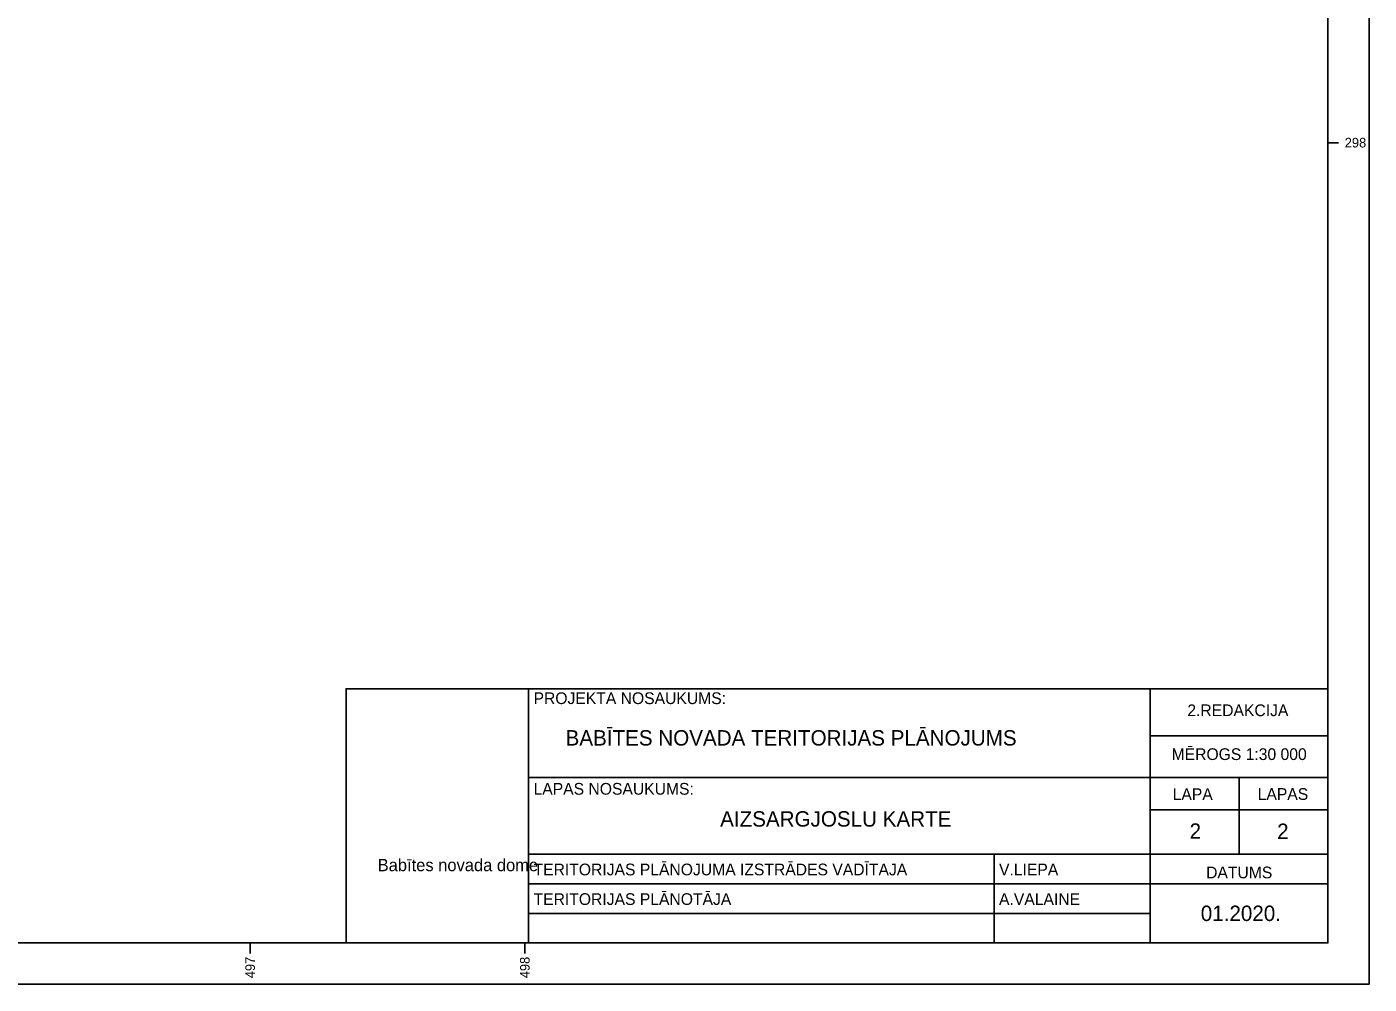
# Model space of a CAD drawing. Extents: x 468834 to 503362, y 294936 to 320859.
# Drawn here: x 496187 to 501073, y 294936 to 298422 of the extents above; entities that cross this region are included whole.
import ezdxf

# ---------------------------------------------------------------- set-up
doc = ezdxf.new("R2010")
doc.units = 0
doc.layers.add('ramis', color=7, linetype='Continuous')
doc.layers.add('Teksts', color=7, linetype='Continuous')

msp = doc.modelspace()

# ---------------------------------------------------------------- linework, layer by layer
at = {"layer": 'ramis'}
for p, q in [((500923.3, 316660.3), (500923.3, 295086.2)), ((500923.3, 298000), (500961.5, 298000)), ((500276.6, 296011.6), (498013.4, 296011.6)), ((500276.6, 296011.6), (500923.3, 296011.6)), ((500923.3, 296011.6), (500923.3, 295409.6)), ((498013.4, 295409.6), (498013.4, 295840.7)), ((498013.4, 295688.3), (500276.6, 295688.3)), ((500276.6, 295688.3), (500923.3, 295688.3)), ((500276.6, 295688.3), (500600, 295688.3)), ((500276.6, 295688.3), (500600, 295688.3)), ((500600, 295688.3), (500600, 295409.6)), ((500600, 295688.3), (500923.3, 295688.3)), ((500276.6, 295570.9), (500923.3, 295570.9)), ((499708.1, 295409.6), (498013.4, 295409.6)), ((498013.4, 295409.6), (498013.4, 295301.8)), ((499708.1, 295301.8), (499708.1, 295409.6)), ((500276.6, 295409.6), (499708.1, 295409.6)), ((500923.3, 295409.6), (500276.6, 295409.6)), ((500923.3, 295301.8), (500923.3, 295409.6)), ((499708.1, 295301.8), (498013.4, 295301.8)), ((498013.4, 295301.8), (498013.4, 295194)), ((498013.4, 295301.8), (499708.1, 295301.8)), ((499708.1, 295194), (499708.1, 295301.8)), ((500276.6, 295301.8), (499708.1, 295301.8)), ((499708.1, 295301.8), (500276.6, 295301.8)), ((500276.6, 295301.8), (500923.3, 295301.8)), ((500923.3, 295194), (500923.3, 295301.8)), ((500923.3, 295086.2), (500923.3, 295240.2)), ((500923.3, 295240.2), (500923.3, 295086.2)), ((500923.3, 295086.2), (500923.3, 295240.2)), ((498013.4, 295194), (498013.4, 295086.2)), ((498013.4, 295086.2), (498013.4, 295194)), ((499708.1, 295194), (498013.4, 295194)), ((498013.4, 295194), (498013.4, 295086.2)), ((498013.4, 295194), (499708.1, 295194)), ((499708.1, 295086.2), (499708.1, 295194)), ((500276.6, 295194), (499708.1, 295194)), ((499708.1, 295194), (500276.6, 295194)), ((500923.3, 295086.2), (500923.3, 295194)), ((500923.3, 295194), (500923.3, 295086.2)), ((500923.3, 295086.2), (500923.3, 295194)), ((500923.3, 295086.2), (468983.8, 295086.2)), ((496766.2, 295086.2), (496766.2, 295086.2)), ((496766.2, 295086.2), (499187.2, 295086.2)), ((499187.2, 295086.2), (496766.2, 295086.2)), ((499187.2, 295086.2), (496766.2, 295086.2)), ((496766.2, 295086.2), (496766.2, 295086.2)), ((496766.2, 295086.2), (499187.2, 295086.2)), ((496766.2, 295086.2), (499187.2, 295086.2)), ((497000, 295086.2), (497000, 295048.1)), ((498000, 295086.2), (498000, 295048.1)), ((498013.4, 295086.2), (498013.4, 295086.2)), ((498013.4, 295086.2), (499708.1, 295086.2)), ((499708.1, 295086.2), (498013.4, 295086.2)), ((499708.1, 295086.2), (498013.4, 295086.2)), ((498013.4, 295086.2), (498013.4, 295086.2)), ((498013.4, 295086.2), (499708.1, 295086.2)), ((498013.4, 295086.2), (499708.1, 295086.2)), ((499187.2, 295086.2), (499187.2, 295086.2)), ((499187.2, 295086.2), (499187.2, 295086.2)), ((499187.2, 295086.2), (499187.2, 295086.2)), ((499187.2, 295086.2), (499999.5, 295086.2)), ((499999.5, 295086.2), (499187.2, 295086.2)), ((499999.5, 295086.2), (499187.2, 295086.2)), ((499187.2, 295086.2), (499187.2, 295086.2)), ((499187.2, 295086.2), (499999.5, 295086.2)), ((499187.2, 295086.2), (499999.5, 295086.2)), ((499708.1, 295086.2), (499708.1, 295086.2)), ((499708.1, 295086.2), (499708.1, 295086.2)), ((499708.1, 295086.2), (499708.1, 295086.2)), ((499708.1, 295086.2), (500276.6, 295086.2)), ((500276.6, 295086.2), (499708.1, 295086.2)), ((500276.6, 295086.2), (499708.1, 295086.2)), ((499708.1, 295086.2), (499708.1, 295086.2)), ((499708.1, 295086.2), (500276.6, 295086.2)), ((499708.1, 295086.2), (500276.6, 295086.2)), ((499923.1, 295086.2), (499923.1, 295086.2)), ((499923.1, 295086.2), (499923.1, 295086.2)), ((499999.5, 295086.2), (500923.3, 295086.2)), ((500923.3, 295086.2), (499999.5, 295086.2)), ((500923.3, 295086.2), (499999.5, 295086.2)), ((499999.5, 295086.2), (500923.3, 295086.2)), ((499999.5, 295086.2), (500923.3, 295086.2)), ((500223.1, 295086.2), (500223.1, 295086.2)), ((500223.1, 295086.2), (500223.1, 295086.2)), ((500276.6, 295086.2), (500923.3, 295086.2)), ((500923.3, 295086.2), (500276.6, 295086.2)), ((500923.3, 295086.2), (500276.6, 295086.2)), ((500276.6, 295086.2), (500923.3, 295086.2)), ((500276.6, 295086.2), (500923.3, 295086.2)), ((500923.3, 295086.2), (500923.3, 295086.2)), ((500923.3, 295086.2), (500923.3, 295086.2)), ((500923.3, 295086.2), (500923.3, 295086.2)), ((500923.3, 295086.2), (500923.3, 295086.2)), ((500923.3, 295086.2), (500923.3, 295086.2)), ((500923.3, 295086.2), (500923.3, 295086.2))]:
    msp.add_line(p, q, dxfattribs=at)
for points in [[(501073.3, 316810.3), (468833.8, 316810.3), (468833.8, 294936.2), (501073.3, 294936.2)], [(500923.3, 296011.6), (497348.8, 296011.6), (497348.8, 295086.2), (500923.3, 295086.2)], [(498013.4, 296011.6), (500276.6, 296011.6), (500276.6, 295688.3), (498013.4, 295688.3)], [(500276.6, 296011.6), (500923.3, 296011.6), (500923.3, 295688.3), (500276.6, 295688.3)], [(500276.6, 295840.7), (500923.3, 295840.7), (500923.3, 295409.6), (500276.6, 295409.6)], [(498013.4, 295688.3), (500276.6, 295688.3), (500276.6, 295409.6), (498013.4, 295409.6)], [(500276.6, 295409.6), (500923.3, 295409.6), (500923.3, 295086.2), (500276.6, 295086.2)]]:
    msp.add_lwpolyline(points, close=True, dxfattribs=at)

# ---------------------------------------------------------------- texts
msp.add_text('298', height=35, dxfattribs=at).set_placement((500984.5, 297982.6))
for s, p in [('497', (497017, 294957.8)), ('498', (498017, 294957.8))]:
    msp.add_text(s, height=35, rotation=90, dxfattribs=at).set_placement(p)
at = {"layer": 'Teksts'}
for s, height, p in [('PROJEKTA NOSAUKUMS:', 42.679, (498031.3, 295956)), ('2.REDAKCIJA', 42.679, (500411.4, 295912)), ('BABĪTES NOVADA TERITORIJAS PLĀNOJUMS', 56.086, (498147.9, 295805)), ('MĒROGS 1:30 000', 42.679, (500354.2, 295752.3)), ('LAPAS NOSAUKUMS:', 42.679, (498031.3, 295626.1)), ('LAPA', 42.68, (500358, 295606.5)), ('LAPAS', 42.68, (500667.5, 295607.2)), ('AIZSARGJOSLU KARTE', 56.086, (498710.6, 295509.8)), ('2', 56.1, (500419.7, 295465.5)), ('2', 56.1, (500738.2, 295464.8)), ('Babītes novada dome', 44.906, (497463.8, 295347.5)), ('TERITORIJAS PLĀNOJUMA IZSTRĀDES VADĪTAJA ', 42.679, (498031.3, 295332.4)), ('V.LIEPA', 42.68, (499725.9, 295332.4)), ('DATUMS', 42.68, (500479.8, 295321.6)), ('TERITORIJAS PLĀNOTĀJA', 42.679, (498031.3, 295224.6)), ('A.VALAINE', 42.68, (499725.9, 295224.6)), ('01.2020.', 56.09, (500460.3, 295166.1))]:
    msp.add_text(s, height=height, dxfattribs=at).set_placement(p)

doc.saveas('drawing.dxf')
